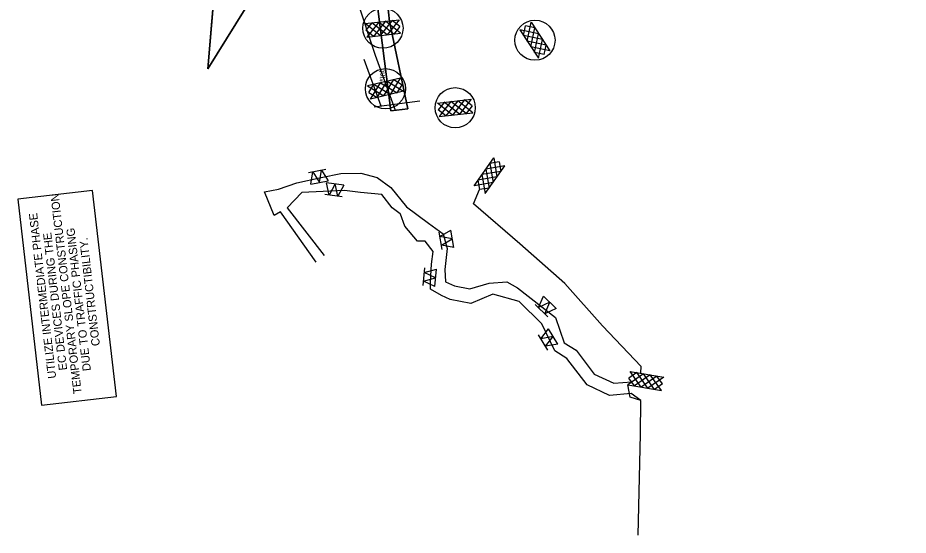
# Model space of a CAD drawing. Extents: x 400935 to 481562, y 415700 to 505362.
# Drawn here: x 474306 to 475062, y 503398 to 503837 of the extents above; entities that cross this region are included whole.
import ezdxf

# ---------------------------------------------------------------- set-up
doc = ezdxf.new("R2010")
doc.units = 0
for name, color, linetype in [('Old_Level_2', 7, 'Continuous'), ('Rock Silt Check Type A Both CELL', 7, 'Continuous'), ('Rock Silt Check Type A Final CELL', 7, 'Continuous'), ('Rock Silt Check Type A with Matting and PAM Final CELL', 7, 'Continuous'), ('Scratch_Level_3', 7, 'Continuous'), ('Scratch_Level_4', 7, 'Continuous'), ('Special Sediment Control Fence Section CG CELL', 7, 'Continuous'), ('Temporary Silt Fence Both', 7, 'Continuous'), ('Temporary Silt Fence CG', 7, 'Continuous'), ('Temporary Silt Fence Final', 7, 'Continuous')]:
    doc.layers.add(name, color=color, linetype=linetype)

msp = doc.modelspace()

# ---------------------------------------------------------------- linework, layer by layer
at = {"layer": 'Old_Level_2'}
for p, q in [((474631.01, 503786.1), (474602.87, 503779.53)), ((474602.87, 503779.53), (474616.74, 503770.91)), ((474604.18, 503773.88), (474608.52, 503780.85)), ((474605.5, 503768.29), (474614.12, 503782.16)), ((474608.52, 503780.85), (474622.39, 503772.23)), ((474611.15, 503769.59), (474619.77, 503783.48)), ((474614.12, 503782.16), (474628.04, 503773.55)), ((474616.74, 503770.91), (474625.41, 503784.8)), ((474619.77, 503783.48), (474633.64, 503774.86)), ((474622.39, 503772.23), (474631.01, 503786.1)), ((474625.41, 503784.8), (474632.34, 503780.46)), ((474628.08, 503773.61), (474632.34, 503780.46)), ((474604.18, 503773.88), (474611.15, 503769.59)), ((474633.64, 503774.86), (474605.5, 503768.29))]:
    msp.add_line(p, q, dxfattribs=at)
msp.add_lwpolyline([(474390.05, 503515.99), (474369.83, 503690.56), (474306.34, 503683.21), (474326.56, 503508.64)], close=True, dxfattribs=at)
msp.add_circle((474618.24, 503777.06), 17.04, dxfattribs=at)
at = {"layer": 'Rock Silt Check Type A Both CELL'}
for p, q in [((474837.18, 503535.2), (474823.83, 503525.79)), ((474831.41, 503536.15), (474824.81, 503531.51)), ((474829.5, 503524.81), (474824.81, 503531.51)), ((474825.8, 503537.18), (474854.28, 503532.24)), ((474835.21, 503523.82), (474825.8, 503537.18)), ((474842.9, 503534.21), (474829.5, 503524.81)), ((474840.93, 503522.83), (474831.47, 503536.19)), ((474848.57, 503533.25), (474835.21, 503523.82)), ((474846.59, 503521.85), (474837.18, 503535.2)), ((474854.28, 503532.24), (474840.93, 503522.83)), ((474852.31, 503520.86), (474842.9, 503534.21)), ((474853.31, 503526.58), (474848.57, 503533.25)), ((474823.83, 503525.79), (474852.31, 503520.86)), ((474853.31, 503526.58), (474846.59, 503521.85))]:
    msp.add_line(p, q, dxfattribs=at)
at = {"layer": 'Rock Silt Check Type A Final CELL'}
for p, q in [((474693.37, 503694.74), (474710.11, 503718.3)), ((474702.79, 503688.05), (474719.53, 503711.61)), ((474719.53, 503711.61), (474703.42, 503708.88)), ((474714.81, 503714.98), (474706.74, 503713.58)), ((474706.74, 503713.58), (474709.48, 503697.46)), ((474710.11, 503718.3), (474712.84, 503702.19)), ((474714.81, 503714.98), (474716.17, 503706.88)), ((474716.17, 503706.88), (474700.07, 503704.15)), ((474700.07, 503704.15), (474702.79, 503688.05)), ((474703.42, 503708.88), (474706.12, 503692.74)), ((474709.48, 503697.46), (474693.37, 503694.74)), ((474712.84, 503702.19), (474696.71, 503699.43)), ((474696.72, 503699.36), (474698.05, 503691.4)), ((474706.12, 503692.74), (474698.05, 503691.4))]:
    msp.add_line(p, q, dxfattribs=at)
at = {"layer": 'Rock Silt Check Type A with Matting and PAM Final CELL'}
for p, q in [((474601.07, 503832.31), (474629.78, 503835.61)), ((474613.86, 503822.15), (474601.07, 503832.31)), ((474606.74, 503832.91), (474601.71, 503826.59)), ((474612.54, 503833.63), (474602.39, 503820.83)), ((474619.62, 503822.81), (474606.78, 503832.96)), ((474618.3, 503834.29), (474608.1, 503821.49)), ((474625.34, 503823.47), (474612.54, 503833.63)), ((474624.02, 503834.96), (474613.86, 503822.15)), ((474631.1, 503824.13), (474618.3, 503834.29)), ((474629.78, 503835.61), (474619.62, 503822.81)), ((474630.45, 503829.89), (474624.02, 503834.96)), ((474738.53, 503817.43), (474741.93, 503833.41)), ((474741.93, 503833.41), (474757.67, 503809.17)), ((474608.1, 503821.49), (474601.71, 503826.59)), ((474630.45, 503829.89), (474625.34, 503823.47)), ((474748.22, 503823.72), (474732.24, 503827.12)), ((474732.24, 503827.12), (474747.98, 503802.88)), ((474735.37, 503822.29), (474737.1, 503830.29)), ((474744.99, 503828.6), (474737.1, 503830.29)), ((474741.69, 503812.57), (474745.06, 503828.58)), ((474602.39, 503820.83), (474631.1, 503824.13)), ((474751.38, 503818.86), (474735.37, 503822.29)), ((474754.52, 503814.04), (474738.53, 503817.43)), ((474744.82, 503807.74), (474748.22, 503823.72)), ((474747.98, 503802.88), (474751.38, 503818.86)), ((474757.67, 503809.17), (474741.69, 503812.57)), ((474752.85, 503806.03), (474754.52, 503814.04)), ((474752.85, 503806.03), (474744.82, 503807.74)), ((474662.36, 503764.86), (474691.07, 503768.15)), ((474675.15, 503754.7), (474662.36, 503764.86)), ((474668.03, 503765.46), (474663.01, 503759.14)), ((474673.84, 503766.17), (474663.68, 503753.38)), ((474680.92, 503755.36), (474668.07, 503765.51)), ((474679.6, 503766.84), (474669.39, 503754.04)), ((474686.63, 503756.02), (474673.84, 503766.17)), ((474685.31, 503767.5), (474675.15, 503754.7)), ((474692.39, 503756.68), (474679.6, 503766.84)), ((474691.07, 503768.15), (474680.92, 503755.36)), ((474691.74, 503762.44), (474685.31, 503767.5)), ((474669.39, 503754.04), (474663.01, 503759.14)), ((474663.68, 503753.38), (474692.39, 503756.68)), ((474691.74, 503762.44), (474686.63, 503756.02))]:
    msp.add_line(p, q, dxfattribs=at)
for centre in [(474616.11, 503828.35), (474745.08, 503818.18), (474677.4, 503760.9)]:
    msp.add_circle(centre, 17.04, dxfattribs=at)
at = {"layer": 'Scratch_Level_3'}
msp.add_lwpolyline([(474626.67, 503758.55), (474609.66, 503805.2), (474594.28, 503852.41)], dxfattribs=at)
at = {"layer": 'Scratch_Level_4'}
for p, q in [((474614.61, 503762.16), (474600.22, 503801.94)), ((474647.49, 503766.61), (474608.56, 503761.34))]:
    msp.add_line(p, q, dxfattribs=at)
msp.add_lwpolyline([(474508.73, 504217.08), (474483.24, 503977.98), (474467.5, 503793.86), (474562.43, 503946.88), (474582.45, 503900.64), (474610.09, 503858.5), (474622.89, 503758.26), (474637.16, 503760.09), (474621.71, 503834.05), (474615.72, 503889.9), (474612.56, 503965.37), (474654.57, 503984.63), (474736.73, 504007.41), (474936.71, 504020.39), (475061.71, 504006.75), (475007.9, 504065.5), (474941.08, 504198.57)], close=True, dxfattribs=at)
for points in [[(474562.43, 503946.88), (474467.5, 503793.86), (474481.43, 503959.46)], [(474615.72, 503889.9), (474621.71, 503834.05), (474637.16, 503760.09), (474622.89, 503758.26), (474610.09, 503858.5)]]:
    msp.add_lwpolyline(points, dxfattribs=at)
at = {"layer": 'Special Sediment Control Fence Section CG CELL'}
for p, q in [((474553.03, 503705.98), (474567.79, 503708.65)), ((474554.81, 503696.14), (474569.57, 503698.81)), ((474582.97, 503695.2), (474568.11, 503697.25)), ((474581.6, 503685.29), (474566.74, 503687.34)), ((474666.43, 503640.48), (474663.76, 503655.25)), ((474676.27, 503642.26), (474673.6, 503657.03)), ((474650.21, 503609.99), (474651.53, 503624.94)), ((474660.18, 503609.12), (474661.49, 503624.06)), ((474763.09, 503590.55), (474752.41, 503601.08)), ((474756.07, 503583.43), (474745.39, 503593.96)), ((474755.87, 503555.25), (474748.12, 503568.1)), ((474764.43, 503560.42), (474756.68, 503573.26))]:
    msp.add_line(p, q, dxfattribs=at)
for points in [[(474554.81, 503696.14), (474556.72, 503706.65), (474562.19, 503697.47)], [(474562.19, 503697.47), (474564.1, 503707.98), (474569.57, 503698.81)], [(474575.54, 503696.22), (474570.46, 503686.83), (474568.11, 503697.25)], [(474582.97, 503695.2), (474577.89, 503685.81), (474575.54, 503696.22)], [(474674.93, 503649.64), (474664.43, 503651.55), (474673.6, 503657.03)], [(474676.27, 503642.26), (474665.76, 503644.17), (474674.93, 503649.64)], [(474660.83, 503616.59), (474651.2, 503621.2), (474661.49, 503624.06)], [(474660.18, 503609.12), (474650.54, 503613.73), (474660.83, 503616.59)], [(474757.75, 503595.82), (474748.06, 503591.33), (474752.41, 503601.08)], [(474763.09, 503590.55), (474753.4, 503586.06), (474757.75, 503595.82)], [(474760.56, 503566.84), (474750.06, 503564.89), (474756.68, 503573.26)], [(474764.43, 503560.42), (474753.93, 503558.46), (474760.56, 503566.84)]]:
    msp.add_lwpolyline(points, dxfattribs=at)
at = {"layer": 'Temporary Silt Fence Both'}
msp.add_lwpolyline([(474832.64, 503398.2), (474834.59, 503483.85), (474834.95, 503512.37)], dxfattribs=at)
at = {"layer": 'Temporary Silt Fence CG'}
for points in [[(474559.36, 503629.97), (474529.33, 503672.64), (474523.8, 503669.39), (474515.54, 503689.59), (474527.44, 503691.88), (474542.94, 503697.28), (474563.79, 503701.65), (474580.45, 503705.14), (474597.46, 503705.39), (474611.26, 503701.57), (474622.88, 503693.22), (474636.06, 503676.76), (474654.77, 503663.04), (474667.22, 503653.9), (474670.48, 503641.36), (474668.56, 503623.64), (474669.3, 503613.22), (474676.82, 503609.79), (474689.77, 503607.22), (474706.34, 503612.06), (474721.23, 503613.32), (474730.31, 503608.04), (474762.37, 503583.01), (474769.72, 503561.55), (474780.08, 503555.12), (474795.24, 503534.84), (474812.13, 503527.23), (474827.26, 503528.19), (474827.26, 503528.19)], [(474834.95, 503512.37), (474826.82, 503518.36), (474808.37, 503516.7), (474789.36, 503525.8), (474772.23, 503548), (474761.87, 503554.6), (474751.04, 503577.58), (474731.54, 503596.51), (474709.36, 503602.66), (474690.73, 503594.93), (474673.08, 503598.09), (474665.91, 503601.45), (474656.57, 503606.94), (474656.56, 503613.26), (474657.3, 503628.18), (474658.76, 503639.06), (474651.9, 503647.63), (474645.3, 503647.77), (474634.65, 503660.37), (474631.12, 503670.47), (474630.67, 503670.8), (474623.93, 503675.86), (474615.19, 503687.16), (474597.05, 503689.1), (474583.44, 503690.56), (474565.35, 503689.78), (474547.27, 503689), (474534.78, 503675.84), (474566.28, 503635.62)]]:
    msp.add_lwpolyline(points, dxfattribs=at)
at = {"layer": 'Temporary Silt Fence Final'}
for points in [[(474834.9, 503535.88), (474835.28, 503541.24), (474802.37, 503575.85), (474770.53, 503611.88), (474732.22, 503645.42), (474693.05, 503679.49), (474698.05, 503691.4), (474698.05, 503691.4)], [(474834.95, 503512.37), (474825.93, 503515.4), (474823.83, 503525.79), (474823.83, 503525.79)]]:
    msp.add_lwpolyline(points, dxfattribs=at)

# ---------------------------------------------------------------- texts
at = {"layer": 'Old_Level_2'}
for s, height, rotation, p in [('*Int.', 4.746, 96.55384, (474618.31, 503783.4)), ('TEMPORARY SLOPE CONSTRUCTION', 7, 96.60681, (474360.58, 503518.54)), ('UTILIZE INTERMEDIATE PHASE', 7, 96.60681, (474338.95, 503531.48)), ('DUE TO TRAFFIC PHASING', 7, 96.60681, (474368.41, 503537.89)), ('EC DEVICES DURING THE ', 7, 96.60681, (474348.21, 503538.48)), ('CONSTRUCTIBILITY.', 7, 96.60681, (474376.02, 503559.09))]:
    msp.add_text(s, height=height, rotation=rotation, dxfattribs=at).set_placement(p)

doc.saveas('drawing.dxf')
